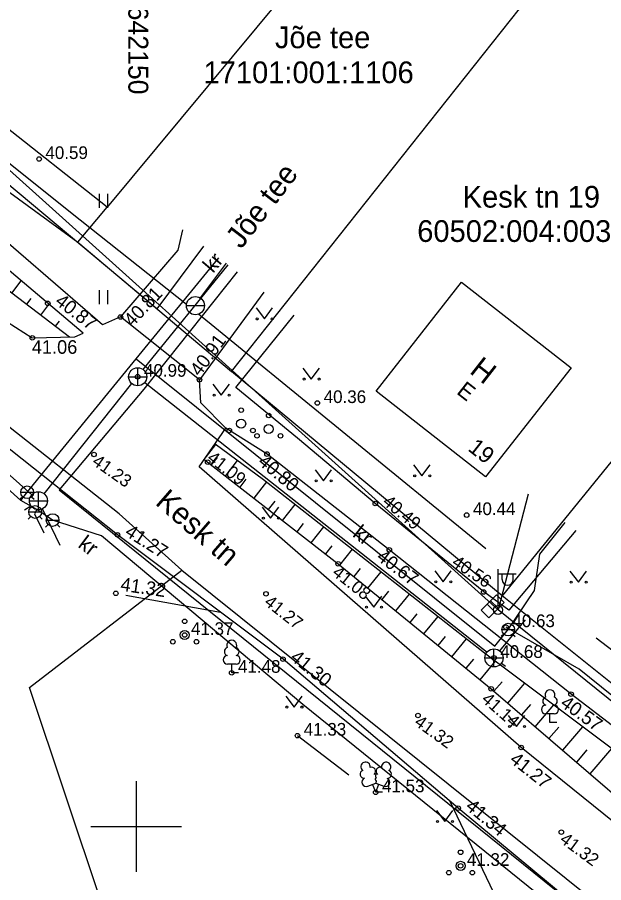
# Model space of a CAD drawing. Extents: x 641898 to 642452, y 6471715 to 6472255.
# Drawn here: x 642143.44 to 642175.81, y 6471946.9 to 6471994.68 of the extents above; entities that cross this region are included whole.
import ezdxf

# ---------------------------------------------------------------- set-up
doc = ezdxf.new("R2010")
doc.units = 0
for name, color, linetype in [('AED', 7, 'Continuous'), ('ELRAJATISMP', 7, 'Continuous'), ('HALJASTUS', 7, 'Continuous'), ('HOONE', 7, 'Continuous'), ('KKAEV', 7, 'Continuous'), ('KORGUS-EH2000', 7, 'Continuous'), ('KTRASS', 7, 'Continuous'), ('MPOHULIIN', 7, 'Continuous'), ('PIIR', 7, 'Continuous'), ('POST', 7, 'Continuous'), ('PUU', 7, 'Continuous'), ('RELJEEF', 7, 'Continuous'), ('TEE', 7, 'Continuous'), ('TTRASS', 7, 'Continuous'), ('VKAEV', 7, 'Continuous'), ('VORK', 7, 'Continuous'), ('VTRASS', 7, 'Continuous')]:
    doc.layers.add(name, color=color, linetype=linetype)

msp = doc.modelspace()

# ---------------------------------------------------------------- linework, layer by layer
at = {"layer": 'AED'}
msp.add_lwpolyline([(642174.267, 6471966.341), (642170.572, 6471961.954), (642169.184, 6471962.952), (642163.2, 6471967.834), (642158.907, 6471971.443), (642155.501, 6471974.235), (642158.721, 6471978.231)], dxfattribs=at)
at = {"layer": 'ELRAJATISMP'}
for p, q in [((642169.884, 6471962.796), (642169.049, 6471961.942)), ((642170.311, 6471962.378), (642169.884, 6471962.796)), ((642169.372, 6471962.272), (642169.799, 6471961.854)), ((642169.476, 6471961.524), (642170.311, 6471962.378)), ((642169.561, 6471962.466), (642169.988, 6471962.048)), ((642169.049, 6471961.942), (642169.476, 6471961.524))]:
    msp.add_line(p, q, dxfattribs=at)
at = {"layer": 'HALJASTUS'}
for p, q in [((642147.957, 6471984.928), (642147.957, 6471984.167)), ((642148.412, 6471984.928), (642148.412, 6471984.167)), ((642147.957, 6471979.61), (642147.957, 6471978.849)), ((642148.412, 6471979.61), (642148.412, 6471978.849)), ((642156.618, 6471978.631), (642157.081, 6471978.024)), ((642157.081, 6471978.024), (642157.527, 6471978.631)), ((642159.206, 6471975.315), (642159.67, 6471974.709)), ((642159.67, 6471974.709), (642160.115, 6471975.315)), ((642154.24, 6471974.43), (642154.703, 6471973.823)), ((642154.703, 6471973.823), (642155.149, 6471974.43)), ((642165.314, 6471969.968), (642165.777, 6471969.361)), ((642165.777, 6471969.361), (642166.223, 6471969.968)), ((642159.877, 6471969.699), (642160.341, 6471969.092)), ((642160.341, 6471969.092), (642160.786, 6471969.699)), ((642156.962, 6471967.638), (642157.425, 6471967.031)), ((642157.425, 6471967.031), (642157.871, 6471967.638)), ((642166.484, 6471964.116), (642166.948, 6471963.51)), ((642166.948, 6471963.51), (642167.393, 6471964.116)), ((642173.947, 6471964.091), (642174.411, 6471963.485)), ((642174.411, 6471963.485), (642174.856, 6471964.091)), ((642162.65, 6471962.719), (642163.114, 6471962.112)), ((642163.114, 6471962.112), (642163.559, 6471962.719)), ((642158.264, 6471957.203), (642158.728, 6471956.597)), ((642158.728, 6471956.597), (642159.173, 6471957.203)), ((642170.541, 6471956.129), (642171.004, 6471955.522)), ((642171.004, 6471955.522), (642171.45, 6471956.129)), ((642158.904, 6471955.017), (642161.741, 6471952.85)), ((642166.574, 6471950.886), (642167.038, 6471950.28)), ((642167.038, 6471950.28), (642167.483, 6471950.886))]:
    msp.add_line(p, q, dxfattribs=at)
msp.add_lwpolyline([(642182.798, 6471951.948), (642174.449, 6471958.694), (642170.419, 6471961.008)], dxfattribs=at)
for centre in [(642156.68, 6471978.024), (642157.509, 6471978.024), (642159.269, 6471974.709), (642160.097, 6471974.709), (642154.302, 6471973.823), (642155.131, 6471973.823), (642165.376, 6471969.361), (642166.205, 6471969.361), (642159.94, 6471969.092), (642160.769, 6471969.092), (642157.024, 6471967.031), (642157.853, 6471967.031), (642166.547, 6471963.51), (642167.376, 6471963.51), (642174.01, 6471963.485), (642174.838, 6471963.485), (642162.713, 6471962.112), (642163.541, 6471962.112), (642158.326, 6471956.597), (642159.155, 6471956.597), (642170.603, 6471955.522), (642171.432, 6471955.522), (642166.637, 6471950.28), (642167.465, 6471950.28)]:
    msp.add_circle(centre, 0.055, dxfattribs=at)
at = {"layer": 'HOONE'}
msp.add_lwpolyline([(642169.284, 6471969.307), (642163.243, 6471974.037), (642167.964, 6471980.055), (642174.004, 6471975.325), (642169.284, 6471969.307)], dxfattribs=at)
at = {"layer": 'KKAEV'}
for p, q in [((642150.088, 6471974.334), (642150.088, 6471975.334)), ((642149.588, 6471974.834), (642150.588, 6471974.834)), ((642144.61, 6471967.486), (642144.61, 6471968.486)), ((642144.11, 6471967.986), (642145.11, 6471967.986)), ((642169.753, 6471958.809), (642169.753, 6471959.809)), ((642169.253, 6471959.309), (642170.253, 6471959.309))]:
    msp.add_line(p, q, dxfattribs=at)
for centre in [(642150.088, 6471974.834), (642144.61, 6471967.986), (642169.753, 6471959.309)]:
    msp.add_circle(centre, 0.5, dxfattribs=at)
at = {"layer": 'KORGUS-EH2000'}
for centre in [(642144.645, 6471986.856), (642145.123, 6471978.889), (642149.137, 6471978.135), (642144.269, 6471976.984), (642150.088, 6471974.834), (642153.495, 6471974.667), (642160.003, 6471973.383), (642147.676, 6471970.544), (642157.225, 6471970.564), (642153.95, 6471970.118), (642163.2, 6471967.834), (642168.246, 6471967.196), (642148.973, 6471966.102), (642163.973, 6471965.281), (642161.15, 6471964.505), (642148.88, 6471962.874), (642157.166, 6471962.844), (642169.184, 6471962.952), (642170.419, 6471961.008), (642152.679, 6471960.577), (642169.753, 6471959.309), (642158.111, 6471959.24), (642155.277, 6471958.487), (642169.596, 6471957.601), (642174.008, 6471957.307), (642165.558, 6471956.127), (642158.904, 6471955.017), (642171.256, 6471954.365), (642163.223, 6471951.89), (642167.777, 6471951.014), (642173.472, 6471949.689), (642167.909, 6471947.828)]:
    msp.add_circle(centre, 0.125, dxfattribs=at)
at = {"layer": 'KTRASS'}
for points in [[(642150.384, 6471975.237), (642155.085, 6471981.012)], [(642155.58, 6471980.633), (642150.419, 6471974.152), (642145.759, 6471968.585), (642185.052, 6471936.9), (642224.346, 6471905.214)], [(642144.236, 6471968.318), (642137.565, 6471974.255)], [(642144.921, 6471968.377), (642149.758, 6471974.459)], [(642150.476, 6471974.519), (642169.374, 6471959.635)], [(642143.842, 6471967.489), (642144.19, 6471967.714)], [(642145.817, 6471965.521), (642144.83, 6471967.537)], [(642170.072, 6471959.694), (642171.49, 6471961.421)], [(642170.164, 6471959.024), (642170.395, 6471958.849)]]:
    msp.add_lwpolyline(points, dxfattribs=at)
at = {"layer": 'MPOHULIIN'}
for points in [[(642355.522, 6471813.313), (642331.534, 6471832.393), (642302.222, 6471855.921), (642271.629, 6471880.301), (642234.793, 6471909.555), (642198.436, 6471939.015), (642169.975, 6471961.956), (642133.076, 6471995.171), (642102.99, 6472021.089), (642074.552, 6472045.947), (642044.597, 6472041.824), (642019.939, 6472060.923), (641980.015, 6472091.706), (641945.513, 6472065.466), (641932.178, 6472056.628)], [(642171.631, 6471968.358), (642169.975, 6471961.956)]]:
    msp.add_lwpolyline(points, dxfattribs=at)
at = {"layer": 'PIIR'}
for p, q in [((642148.4, 6471984.2), (642083.42, 6472035.57)), ((642111.27, 6472008.25), (642146.78, 6471982.26)), ((642164.726, 6472003.848), (642148.4, 6471984.2)), ((642155.27, 6471975.12), (642173.332, 6471997.892)), ((642149.07, 6471967.26), (642119.65, 6471990.44)), ((642189.602, 6471986.63), (642170.2, 6471962.73)), ((642146.78, 6471982.26), (642148.4, 6471984.2)), ((642146.78, 6471982.26), (642155.27, 6471975.12)), ((642170.2, 6471962.73), (642155.27, 6471975.12)), ((642152.53, 6471964.16), (642149.07, 6471967.26)), ((642144.12, 6471957.68), (642152.53, 6471964.16)), ((642152.53, 6471964.16), (642179.85, 6471942.23)), ((642186.7, 6471949.52), (642170.2, 6471962.73)), ((642150.25, 6471939.32), (642144.12, 6471957.68))]:
    msp.add_line(p, q, dxfattribs=at)
at = {"layer": 'POST'}
for p, q in [((642169.975, 6471962.206), (642169.975, 6471964.206)), ((642169.975, 6471963.956), (642170.975, 6471963.956)), ((642170.202, 6471963.635), (642170.202, 6471963.956)), ((642170.814, 6471963.635), (642170.814, 6471963.956))]:
    msp.add_line(p, q, dxfattribs=at)
msp.add_circle((642169.975, 6471961.956), 0.25, dxfattribs=at)
msp.add_arc((642170.508, 6471963.635), 0.306, 180, 0, dxfattribs=at)
at = {"layer": 'PUU'}
for p, q in [((642155.517, 6471958.962), (642155.037, 6471958.962)), ((642155.277, 6471958.487), (642155.277, 6471958.962)), ((642155.657, 6471958.487), (642155.277, 6471958.487)), ((642173.083, 6471956.226), (642172.603, 6471956.226)), ((642172.843, 6471955.751), (642172.843, 6471956.226)), ((642173.223, 6471955.751), (642172.843, 6471955.751)), ((642162.783, 6471952.225), (642163.228, 6471952.4)), ((642163.223, 6471951.89), (642163.048, 6471952.33)), ((642163.223, 6471951.89), (642163.403, 6471952.33)), ((642163.228, 6471952.4), (642163.668, 6471952.22)), ((642163.603, 6471951.89), (642163.223, 6471951.89))]:
    msp.add_line(p, q, dxfattribs=at)
msp.add_lwpolyline([(642163.228, 6471952.895), (642163.208, 6471952.82), (642163.208, 6471952.8), (642163.218, 6471952.77), (642163.238, 6471952.735), (642163.243, 6471952.715), (642163.228, 6471952.68), (642163.203, 6471952.63), (642163.198, 6471952.605), (642163.203, 6471952.59), (642163.213, 6471952.56), (642163.248, 6471952.5), (642163.253, 6471952.48), (642163.248, 6471952.46), (642163.233, 6471952.425), (642163.228, 6471952.4)], dxfattribs=at)
for centre, radius in [((642155.797, 6471972.989), 0.125), ((642157.32, 6471972.698), 0.125), ((642155.797, 6471972.239), 0.25), ((642155.147, 6471971.864), 0.125), ((642156.447, 6471971.864), 0.125), ((642157.32, 6471971.948), 0.25), ((642156.67, 6471971.573), 0.125), ((642157.97, 6471971.573), 0.125), ((642152.679, 6471961.327), 0.125), ((642152.679, 6471960.577), 0.25), ((642152.029, 6471960.202), 0.125), ((642153.329, 6471960.202), 0.125), ((642167.909, 6471948.578), 0.125), ((642167.909, 6471947.828), 0.25), ((642167.259, 6471947.453), 0.125), ((642168.559, 6471947.453), 0.125)]:
    msp.add_circle(centre, radius, dxfattribs=at)
for centre, radius, start, end in [((642155.107, 6471959.66), 0.233, 109.0217, 253.1415), ((642155.277, 6471960.007), 0.277, 332.5799, 207.4201), ((642155.447, 6471959.66), 0.233, 286.8508, 70.9859), ((642155.04, 6471959.199), 0.238, 90.0016, 269.3953), ((642155.514, 6471959.199), 0.238, 270.6047, 89.9984), ((642172.843, 6471957.271), 0.277, 332.5799, 207.4201), ((642172.673, 6471956.924), 0.233, 109.0217, 253.1415), ((642173.013, 6471956.924), 0.233, 286.8508, 70.9859), ((642172.606, 6471956.463), 0.238, 90.0016, 269.3953), ((642173.08, 6471956.463), 0.238, 270.6047, 89.9984), ((642162.666, 6471953.304), 0.256, 111.5027, 232.5173), ((642162.666, 6471953.304), 0.256, 350.4856, 111.5002), ((642163.001, 6471953.054), 0.224, 308.5041, 111.5725), ((642163.464, 6471953.049), 0.225, 67.7016, 230.5126), ((642163.802, 6471953.295), 0.256, 67.6168, 188.6314), ((642163.802, 6471953.295), 0.256, 306.5997, 67.6143), ((642162.592, 6471952.893), 0.224, 111.4304, 274.4987), ((642163.227, 6471952.657), 0.237, 66.7655, 111.5015), ((642163.869, 6471952.883), 0.224, 264.6183, 67.6866), ((642162.697, 6471952.448), 0.237, 111.5014, 291.5004), ((642163.758, 6471952.44), 0.237, 247.6166, 67.6155)]:
    msp.add_arc(centre, radius, start, end, dxfattribs=at)
at = {"layer": 'RELJEEF'}
for p, q in [((642143.148, 6471979.448), (642143.663, 6471980.124)), ((642144.185, 6471979.16), (642143.944, 6471978.842)), ((642144.739, 6471978.237), (642145.192, 6471978.831)), ((642145.746, 6471977.908), (642145.535, 6471977.631)), ((642153.761, 6471970.265), (642154.402, 6471971.087)), ((642154.469, 6471970.384), (642154.143, 6471969.967)), ((642154.932, 6471969.352), (642155.601, 6471970.211)), ((642156.065, 6471969.179), (642155.721, 6471968.738)), ((642156.509, 6471968.123), (642157.212, 6471969.024)), ((642157.648, 6471967.957), (642157.298, 6471967.508)), ((642158.087, 6471966.893), (642158.785, 6471967.789)), ((642159.223, 6471966.724), (642158.875, 6471966.278)), ((642159.664, 6471965.663), (642160.357, 6471966.553)), ((642160.799, 6471965.491), (642160.453, 6471965.049)), ((642161.24, 6471964.432), (642161.942, 6471965.308)), ((642162.375, 6471964.241), (642162.014, 6471963.799)), ((642162.788, 6471963.166), (642163.524, 6471964.066)), ((642163.936, 6471962.99), (642163.562, 6471962.533)), ((642164.337, 6471961.9), (642165.097, 6471962.83)), ((642165.497, 6471961.74), (642165.111, 6471961.267)), ((642165.885, 6471960.634), (642166.67, 6471961.594)), ((642167.058, 6471960.489), (642166.659, 6471960.001)), ((642167.434, 6471959.369), (642168.242, 6471960.358)), ((642168.618, 6471959.238), (642168.208, 6471958.736)), ((642168.982, 6471958.103), (642169.829, 6471959.133)), ((642170.198, 6471957.994), (642169.753, 6471957.466)), ((642170.512, 6471956.815), (642171.455, 6471957.914)), ((642171.764, 6471956.738), (642171.271, 6471956.163)), ((642172.029, 6471955.512), (642173.059, 6471956.711)), ((642173.324, 6471955.485), (642172.788, 6471954.861)), ((642173.547, 6471954.209), (642174.662, 6471955.509)), ((642174.885, 6471954.233), (642174.306, 6471953.558)), ((642175.064, 6471952.906), (642176.266, 6471954.306))]:
    msp.add_line(p, q, dxfattribs=at)
for points in [[(642146.331, 6471977.025), (642136.065, 6471984.84), (642127.477, 6471991.602), (642117.617, 6471999.493), (642106.697, 6472008.186)], [(642153.761, 6471970.265), (642161.15, 6471964.505), (642169.596, 6471957.601), (642178.247, 6471950.174), (642186.952, 6471943.184), (642196.672, 6471935.377), (642206.377, 6471928.027)]]:
    msp.add_lwpolyline(points, dxfattribs=at)
at = {"layer": 'TEE'}
for points in [[(642248.038, 6471894.359), (642244.819, 6471896.591), (642243.421, 6471898.287), (642241.287, 6471898.567), (642230.451, 6471907.231), (642220.045, 6471915.264), (642210.382, 6471923.001), (642201.484, 6471930.096), (642191.341, 6471938.065), (642180.941, 6471946.534), (642171.256, 6471954.365), (642153.477, 6471969.856), (642154.958, 6471971.99), (642153.566, 6471973.386), (642153.495, 6471974.667), (642149.137, 6471978.135), (642148.146, 6471977.701), (642140.89, 6471983.962), (642132.244, 6471991.056), (642124.462, 6471997.136), (642114.29, 6472005.762), (642111.738, 6472008.121), (642108.086, 6472011.066)], [(642116.8, 6471997.886), (642127.037, 6471989.838), (642135.887, 6471982.715), (642142.876, 6471977.864), (642144.269, 6471976.984), (642146.619, 6471977.031), (642147.081, 6471977.233), (642138.426, 6471984.553), (642131.75, 6471990.028), (642121.917, 6471997.85)], [(642253.944, 6471882.162), (642243.566, 6471890.342), (642234.582, 6471897.491), (642228.739, 6471901.846), (642227.951, 6471901.93), (642224.85, 6471904.256), (642224.883, 6471905.449), (642215.573, 6471912.361), (642205.766, 6471920.313), (642195.477, 6471928.355), (642185.674, 6471936.257), (642176.022, 6471944.175), (642167.777, 6471951.014), (642158.111, 6471959.24), (642148.973, 6471966.102), (642138.436, 6471974.464), (642128.627, 6471982.536), (642127.755, 6471983.25), (642118.56, 6471990.787)], [(642152.558, 6471982.945), (642152.312, 6471981.831), (642149.137, 6471978.135)], [(642157.056, 6471979.505), (642153.495, 6471974.667)], [(642214.441, 6471935.082), (642210.265, 6471931.295), (642208.667, 6471929.555), (642200.55, 6471936.024), (642192.814, 6471942.275), (642187.251, 6471946.896), (642181.726, 6471951.396), (642174.008, 6471957.307), (642163.973, 6471965.281), (642157.225, 6471970.564), (642154.958, 6471971.99)], [(642154.355, 6471971.122), (642157.028, 6471969.169), (642169.227, 6471959.585), (642186.663, 6471946.509), (642193.917, 6471940.248), (642200.688, 6471934.7), (642208.235, 6471929.084), (642207.681, 6471928.481), (642204.777, 6471927.47)], [(642149.425, 6471962.775), (642154.659, 6471961.828)], [(642169.743, 6471946.343), (642169.138, 6471947.605), (642167.311, 6471951.41)]]:
    msp.add_lwpolyline(points, dxfattribs=at)
at = {"layer": 'TTRASS'}
msp.add_lwpolyline([(642153.724, 6471982.053), (642151.153, 6471978.584), (642135.818, 6471991.407)], dxfattribs=at)
at = {"layer": 'VKAEV'}
for p, q in [((642152.774, 6471978.759), (642153.774, 6471978.759)), ((642143.74, 6471968.207), (642143.6, 6471968.067)), ((642143.637, 6471968.454), (642144.337, 6471968.454)), ((642144.234, 6471968.207), (642144.374, 6471968.067)), ((642144.182, 6471967.119), (642144.042, 6471966.979)), ((642144.079, 6471967.366), (642144.779, 6471967.366)), ((642144.676, 6471967.119), (642144.816, 6471966.979)), ((642145.147, 6471966.674), (642145.007, 6471966.534)), ((642145.044, 6471966.921), (642145.744, 6471966.921)), ((642145.641, 6471966.674), (642145.781, 6471966.534)), ((642170.186, 6471960.872), (642170.886, 6471960.872)), ((642170.289, 6471960.625), (642170.149, 6471960.485)), ((642170.783, 6471960.625), (642170.923, 6471960.485))]:
    msp.add_line(p, q, dxfattribs=at)
for centre, radius in [((642153.274, 6471978.759), 0.5), ((642143.987, 6471968.454), 0.35), ((642144.429, 6471967.366), 0.35), ((642145.394, 6471966.921), 0.35), ((642170.536, 6471960.872), 0.35)]:
    msp.add_circle(centre, radius, dxfattribs=at)
at = {"layer": 'VORK'}
for p, q in [((642150, 6471952.5), (642150, 6471947.5)), ((642147.5, 6471950), (642152.5, 6471950))]:
    msp.add_line(p, q, dxfattribs=at)
at = {"layer": 'VTRASS'}
for points in [[(642152.778, 6471978.827), (642146.383, 6471983.907), (642131.71, 6471995.654), (642117.349, 6472008.175)], [(642143.631, 6471968.002), (642144.012, 6471968.484), (642150, 6471975.819), (642154.57, 6471981.406)], [(642154.968, 6471981.102), (642153.537, 6471979.184)], [(642256.057, 6471879.253), (642241.436, 6471890.95), (642226.363, 6471903.005), (642214.466, 6471912.082), (642191.253, 6471930.836), (642159.201, 6471956.73), (642153.648, 6471961.39), (642148.095, 6471966.051), (642145.394, 6471966.921), (642144.516, 6471967.495), (642143.631, 6471968.002), (642136.85, 6471974.118), (642135.798, 6471974.98), (642131.146, 6471978.791)], [(642169.306, 6471965.335), (642153.452, 6471978.292)], [(642150, 6471975.819), (642169.792, 6471959.959), (642170.536, 6471960.872), (642171.986, 6471963.037), (642172.28, 6471965.031), (642173.687, 6471966.785)], [(642144.516, 6471967.495), (642144.397, 6471967.272), (642144.908, 6471966.212)], [(642261.241, 6471893.85), (642226.798, 6471920.874), (642223.555, 6471923.471), (642220.019, 6471926.258), (642175.39, 6471960.391)]]:
    msp.add_lwpolyline(points, dxfattribs=at)

# ---------------------------------------------------------------- texts
at = {"layer": 'HOONE'}
for s, height, p in [('H', 1.2, (642168.349, 6471975.073)), ('E', 0.9, (642167.639, 6471973.933)), ('19', 0.9, (642168.262, 6471970.794))]:
    msp.add_text(s, height=height, rotation=321.9394, dxfattribs=at).set_placement(p)
at = {"layer": 'KORGUS-EH2000'}
for s, height, p in [('40.59', 0.7, (642144.995, 6471986.856)), ('41.06', 0.75, (642144.245, 6471976.101)), ('40.99', 0.7, (642150.438, 6471974.834)), ('40.36', 0.7, (642160.353, 6471973.383)), ('40.44', 0.7, (642168.596, 6471967.196)), ('40.63', 0.7, (642170.769, 6471961.008)), ('41.37', 0.7, (642153.029, 6471960.577)), ('40.68', 0.7, (642170.103, 6471959.309)), ('41.48', 0.7, (642155.627, 6471958.487)), ('41.33', 0.7, (642159.254, 6471955.017)), ('41.53', 0.7, (642163.573, 6471951.89)), ('41.32', 0.7, (642168.259, 6471947.828))]:
    msp.add_text(s, height=height, dxfattribs=at).set_placement(p)
for s, height, rotation, p in [('40.81', 0.75, 46.8479, (642149.794, 6471977.54)), ('40.87', 0.75, 322.4038, (642145.473, 6471978.889)), ('40.91', 0.75, 53.3097, (642153.509, 6471974.811)), ('41.23', 0.7, 324.9344, (642147.519, 6471970.026)), ('41.09', 0.7, 321.7773, (642153.864, 6471970.245)), ('40.80', 0.75, 320.0693, (642156.672, 6471970.042)), ('40.49', 0.7, 320.1775, (642163.55, 6471967.834)), ('41.27', 0.75, 327.8018, (642149.323, 6471966.102)), ('40.67', 0.75, 323.0059, (642163.217, 6471964.767)), ('40.56', 0.7, 326.213, (642167.369, 6471964.446)), ('41.08', 0.7, 321.4826, (642160.771, 6471963.92)), ('41.32', 0.75, 351.5825, (642149.105, 6471963.028)), ('41.27', 0.7, 321.7368, (642157.016, 6471962.287)), ('41.30', 0.75, 321.0374, (642158.461, 6471959.24)), ('41.14', 0.7, 318.6635, (642169.016, 6471956.949)), ('40.57', 0.75, 324.0312, (642173.361, 6471956.683)), ('41.32', 0.7, 324.0739, (642165.304, 6471955.64)), ('41.27', 0.75, 321.5738, (642170.566, 6471953.593)), ('41.34', 0.75, 320.2187, (642168.127, 6471951.014)), ('41.32', 0.7, 323.3379, (642173.333, 6471949.171))]:
    msp.add_text(s, height=height, rotation=rotation, dxfattribs=at).set_placement(p)
at = {"layer": 'PIIR'}
for s, p in [('Jõe tee', (642157.665, 6471992.974)), ('17101:001:1106', (642153.722, 6471991.042)), ('Kesk tn 19', (642168.023, 6471984.171)), ('60502:004:0034', (642165.517, 6471982.278))]:
    msp.add_text(s, height=1.2, dxfattribs=at).set_placement(p)
at = {"layer": 'TEE'}
for s, height, rotation, p in [('Jõe tee', 1.2, 52.5723, (642155.801, 6471981.845)), ('kr', 0.85, 49.3394, (642154.247, 6471980.514)), ('Kesk tn', 1.2, 318.9346, (642151.003, 6471967.819)), ('kr', 0.85, 321.9427, (642161.899, 6471966.054)), ('kr', 0.85, 323.096, (642146.742, 6471965.461))]:
    msp.add_text(s, height=height, rotation=rotation, dxfattribs=at).set_placement(p)
at = {"layer": 'VORK'}
msp.add_text('Y=642150', height=1.1, rotation=270, dxfattribs=at).set_placement((642149.571, 6471997.165))

doc.saveas('drawing.dxf')
